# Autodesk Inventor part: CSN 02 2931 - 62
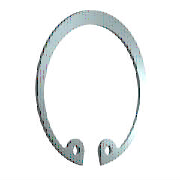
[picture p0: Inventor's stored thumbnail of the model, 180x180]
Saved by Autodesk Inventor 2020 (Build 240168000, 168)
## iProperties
Created: 2019-01
Part Number: CSN 02 2931 - 62
Material: Ocel, měkká
Description: Pojistné kroužky pro otvory
Document SubType Name: Modeling
Standard: CSN 02 2931
Designer: doma
Standards Organization: CSN
Language: cs-CZ
Size Designation: 62
Categories: <MemberInstance><Categories><Category DisplayName="Součásti hřídele" InternalName="7f7aeb1f-a693-4053-b835-cee3144e0d98" Mnemonic="SHFT"><Category DisplayName="
Density: 7.85 g/cm^3
Appearance: Pololeštěná
Mass: 11.7202 g
Surface Area: 22.268 cm^2
Volume: 1.49302 cm^3
IsCustomPart: 0
Author: doma
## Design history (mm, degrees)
sketch "Náčrt1"
  geometry: L1 (0, 15.113)-(0, -73.177) reference; L2 (-45.5, 0)-(45.5, 0) reference; L3 (-4.964, 2.5)-(1.502, 2.5); L4 (0, -3)-(-5.307, -3); L5 (0, -30)-(-13.368, -59.623); L6 (-13.368, -59.623)-(-26.939, -53.499); L7 (-11.949, -56.479)-(-22.5, -51.717); L8 (-9.671, -57.507)-(-11.05, -60.564); L9 (9.671, -57.507)-(11.05, -60.564); C1 r 1.25 at (-11.949, -56.479); C2 r 1.25 at (11.949, -56.479); A1 r 28.375 centre (0, -31.375) between (16.406, -54.527) and (-16.406, -54.527); A2 r 32.5 centre (0, -30) between (11.05, -60.564) and (-11.05, -60.564); A3 r 2.5 centre (-11.949, -56.479) between (-9.671, -57.507) and (-13.455, -54.483); A4 r 2.5 centre (-14.96, -52.487) between (-16.406, -54.527) and (-13.455, -54.483); A5 r 2.5 centre (14.96, -52.487) between (13.455, -54.483) and (16.406, -54.527); A6 r 2.5 centre (11.949, -56.479) between (13.455, -54.483) and (9.671, -57.507); 3 further points
  constraints: 15 point on circle, 14 end point, 9 symmetric about line, 8 centre point, 6 tangent, 4 coincident, 4 point on line, 3 perpendicular, 1 parallel, 4 other
  dimensions: "d8" = 1.375 distance of A1.centre L5.start (= 0.25 x SRB1); "d38" = 5.5 distance between parallel lines of L4 L3 (= SRB1); "d39" = 30 distance from line of L5.start L2 (= 0.5 x WD); "d43" = 32.5 radius of A2 (= 0.5 x ND); "d45" = 3.45 distance between parallel lines of L7 L6 (= 0.5 x SRB2); "d46" = 2.5 radius of A4 (= SD5); "d47" = 11.05 distance from line of L1 L8.end (= 0.17 x ND); "d48" = 2.5 diameter of C1 (= SD5); "d49" = 2.5 radius of A3 (= SD5)
extrude "Těleso" new body sketch "Náčrt1" distance "d2" = 2 (= SD); taper "d3" = 0 deg
workaxis "Work Axis1"
workaxis "Work Axis2"
workplane "Work Plane1"
body "Solid1"
other parameters: "SD" = 2 [user parameter; used in 1 equation term], "SRB1" = 5.5 [user parameter; used in 2 equation terms], "ND" = 65 [user parameter; used in 2 equation terms], "SRB2" = 6.9 [user parameter; used in 1 equation term], "SD5" = 2.5 [user parameter; used in 3 equation terms], "d50" = 0, "d51" = 0, "d52" = 0, "d53" = 0, "SD6" = 66.2 [user parameter], "WDMAX" = 62 (= NND) [user parameter], "NND" = 62 [user parameter; used in 1 equation term]
